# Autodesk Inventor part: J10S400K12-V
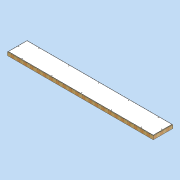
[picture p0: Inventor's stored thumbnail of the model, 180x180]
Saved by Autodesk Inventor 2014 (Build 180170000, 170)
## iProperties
Created: 2011-04
Part Number: J10S400K12-V
Document SubType Name: Modeling
Designer: david.appleford
Density: 1 g/cm^3
Description: Joist Spacer 2.5w x 400mm - Locks 12
Mass: 94203.4 g
Surface Area: 29366.1 cm^2
Volume: 94203.4 cm^3
Cost Center: £120.00
Material: Generic
Appearance: Wood (Pine)
Justset: False
Title: Panel 0.5w x 1w Locks 3
Author: david.appleford
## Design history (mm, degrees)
sketch "Sketch1"
  geometry: L1 (0, 0)-(3050, 0); L2 (3050, 0)-(3050, 468); L3 (3050, 468)-(0, 468); L4 (0, 468)-(0, 0); L5 (34, 434)-(3016, 434); L6 (3016, 434)-(3016, 34); L7 (3016, 34)-(34, 34); L8 (34, 34)-(34, 434)
  constraints: 16 end point, 4 parallel, 2 perpendicular, 1 horizontal, 3 other
  dimensions: "d0" = 3050 distance between parallel lines of L2 L4; "d1" = 468 distance between parallel lines of L1 L3; "d2" = 34 distance between parallel lines of L5 L3 (= 0.5 x t); "d30" = 400 distance between parallel lines of L7 L5 (derived); "d31" = 2982 distance between parallel lines of L6 L8 (derived)
extrude "Extrusion1" new body sketch "Sketch1" distance "d3" = 68 (= t); taper "d4" = 0 deg
sketch "Sketch2"
  geometry: L1 (3016, 434)-(3016, 34) reference; L2 (34, 434)-(3016, 434) reference; L3 (34, 34)-(34, 434) reference; L4 (3016, 34)-(34, 34) reference; L5 (3006, 424)-(3006, 44); L6 (3006, 44)-(44, 44); L7 (44, 44)-(44, 424); L8 (44, 424)-(3006, 424); 1 further point
  constraints: 8 end point, 3 other
  dimensions: "d5" = 10 distance between parallel lines of L8 L2
extrude "Extrusion2" join sketch "Sketch2" distance "d6" = 6 (= sw); taper "d7" = 0 deg
sketch "Sketch3"
  geometry: L1 (-44, 424)-(-3006, 424) reference; L2 (-3006, 424)-(-3006, 44) reference; L3 (-44, 44)-(-44, 424) reference; L4 (-3006, 44)-(-44, 44) reference; 1 further point
extrude "Extrusion3" join sketch "Sketch3" distance "d8" = 6 (= sw); taper "d9" = 0 deg
sketch "Sketch4"
  geometry: L1 (34, 434)-(3016, 434) reference; L2 (3016, 434)-(3016, 34) reference; L3 (3016, 34)-(34, 34) reference; L4 (34, 34)-(34, 434) reference; 13 further points
  constraints: 9 horizontal alignment, 5 vertical alignment
  dimensions: "d10" = 28 distance from line of point (305, 406) L1 (= k); "d12" = 28 distance from line of L3 point (915, 62) (= k); "d13" = 28 distance from line of point (62, 234) L4 (= k); "d14" = 305 horizontal distance of point (305, 406) point (0, 0) (= 0.25 x w); "d15" = 610 horizontal distance of point (915, 62) point (305, 406) (= 0.5 x w); "d29" = 28 distance from line of L2 point (2988, 234) (= d13); "d32" = 400 distance between parallel lines of L3 L1 (derived); "d33" = 200 distance from line of L1 point (62, 234) (= 0.5 x d32); "d47" = 610 distance of point (1525, 406) point (915, 406); "d48" = 610 distance of point (2135, 406) point (1525, 406); "d49" = 610 distance of point (2745, 406) point (2135, 406)
hole "Hole1" sketch "Sketch4" at (305, 406), (62, 234), (915, 62), (2988, 234), (915, 406), (305, 62), (1525, 406), (1525, 62), (2135, 406), (2135, 62), (2745, 406), (2745, 62) diameter "d22" = 12 (= hd); stored, may be unused: countersink angle "d26" = 90 deg, drill point angle "d28" = 118 deg; dims "d23" = 6, "d24" = 4, "d25" = 2, "d27" = 8
sketch "Sketch5"
  geometry: L1 (-3016, 34)-(-34, 34) reference; L2 (-34, 434)-(-3016, 434) reference; L3 (-1176, 34)-(-1264, 34); L4 (-1264, 34)-(-1264, 434); L5 (-1264, 434)-(-1176, 434); L6 (-1176, 434)-(-1176, 34); L7 (-2484, 34)-(-2396, 34); L8 (-2396, 34)-(-2396, 434); L9 (-2396, 434)-(-2484, 434); L10 (-2484, 434)-(-2484, 34); L11 (-1220, 34)-(-1220, 434); L12 (-2440, 34)-(-2440, 434); 1 further point
  constraints: 20 end point, 4 midpoint, 4 point on line
  dimensions: "d41" = 1220 distance between parallel lines of L12 L11; "d42" = 88 distance between parallel lines of L4 L6; "d43" = 88 distance between parallel lines of L10 L8 (= d42); "d44" = 1220 distance from line of point (0, 0) L11 (= d41)
extrude "Extrusion4" cut sketch "Sketch5" stored distance "d45" = 10; taper "d46" = 0 deg
body "Solid1"
node "Projected Loop1"
other parameters: "t" = 68 [user parameter; used in 2 equation terms], "e" = 16 [user parameter], "sw" = 6 [user parameter; used in 2 equation terms], "sc" = 9 [user parameter], "sf" = 12 [user parameter], "k" = 28 [user parameter; used in 3 equation terms], "hd" = 12 [user parameter; used in 1 equation term]
